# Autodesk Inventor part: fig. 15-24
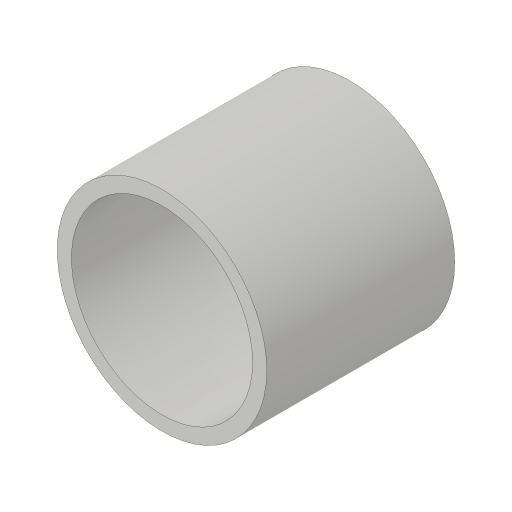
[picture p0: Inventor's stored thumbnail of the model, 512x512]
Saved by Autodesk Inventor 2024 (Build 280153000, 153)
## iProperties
Created: 2018-03
Part Number: fig. 15-24
Material: Generic
Document SubType Name: Modeling
Designer: CADCIM 00
Density: 1 g/cm^3
Appearance: Default
Author: CADCIM 00
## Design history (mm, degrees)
sketch "Sketch1"
  geometry: C1 r 14.209 at (0.32, 0); C2 r 12.286 at (0.32, 0); 1 further point
  constraints: 2 centre point, 1 coincident
extrude "Extrusion1" new body sketch "Sketch1" distance "d0" = 25.5; taper "d1" = 0 deg
body "Solid1"
